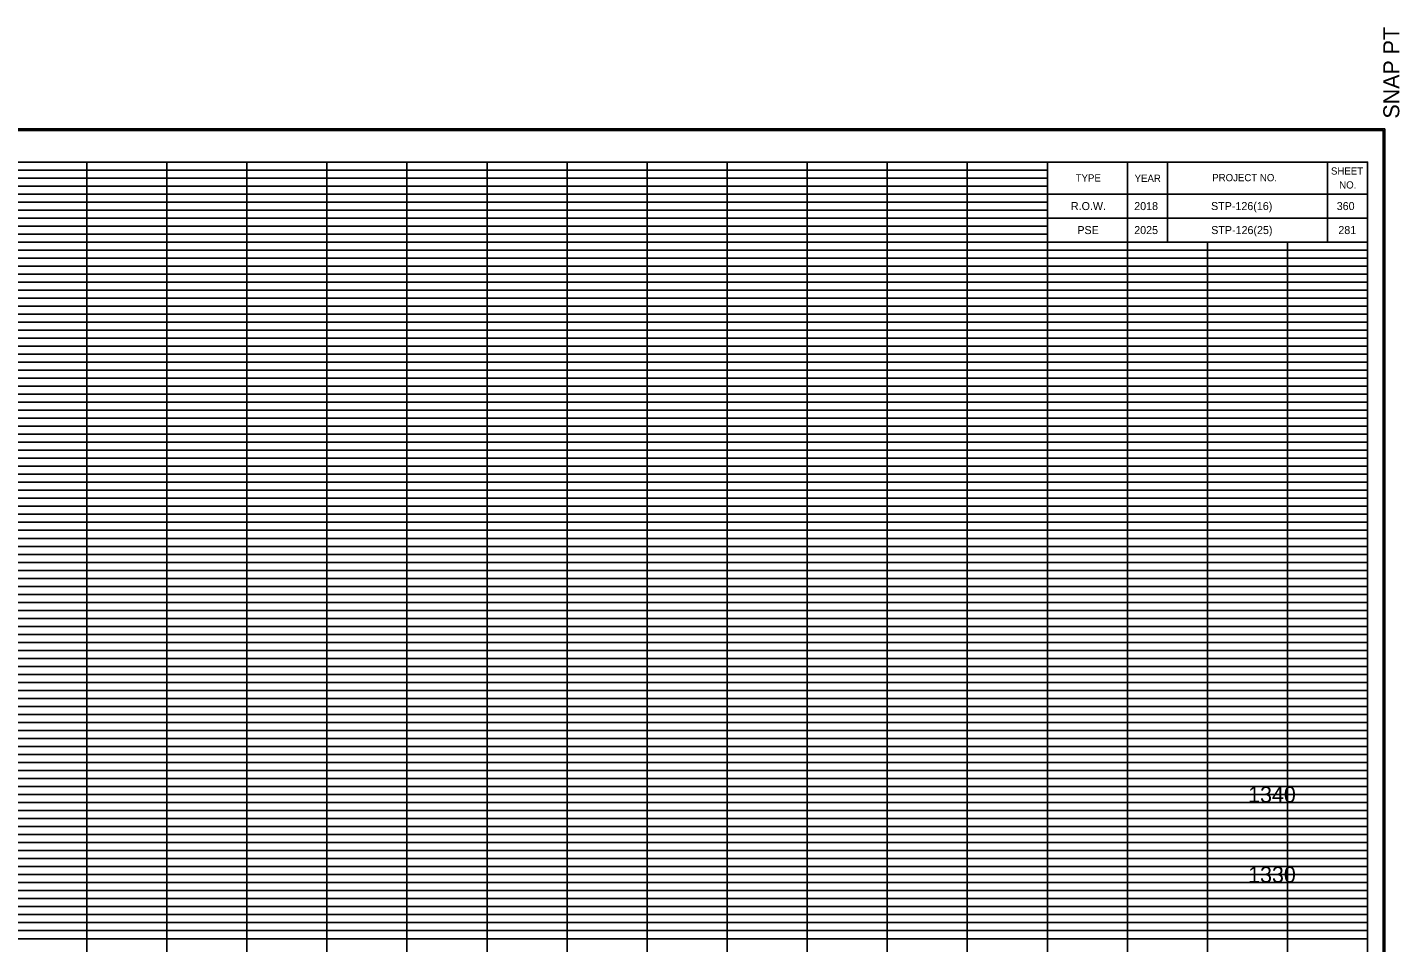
# Model space of a CAD drawing. Extents: x 980 to 1324, y 978 to 2847.
# Drawn here: x 1152.6 to 1324, y 1922.5 to 2036.8 of the extents above; entities that cross this region are included whole.
import ezdxf

# ---------------------------------------------------------------- set-up
doc = ezdxf.new("R2010")
doc.units = 0
for name, color, linetype in [('DESIGN - SCRATCH - User 1', 7, 'Continuous'), ('DESIGN - SHEET - Corner Text', 7, 'Continuous'), ('DESIGN - SHEET - Light Grid', 7, 'Continuous'), ('DESIGN - SHEET - Linework', 7, 'Continuous'), ('DESIGN - SHEET - Plot Shape', 7, 'Continuous'), ('DESIGN - TYPICAL - Text', 7, 'Continuous')]:
    doc.layers.add(name, color=color, linetype=linetype)

# ---------------------------------------------------------------- blocks, each defined once
blk = doc.blocks.new('XSTSHT')
at = {"layer": 'DESIGN - SCRATCH - User 1'}
for p, q in [((28.5, 20.45), (28.5, 20.45)), ((29.24, 20.45), (29.24, 20.45)), ((30.49, 20.45), (30.49, 20.45)), ((31.74, 20.45), (31.74, 20.45)), ((28.5, 20.15), (28.5, 20.15)), ((29.24, 20.15), (29.24, 20.15)), ((30.49, 20.15), (30.49, 20.15)), ((31.74, 20.15), (31.74, 20.15))]:
    blk.add_line(p, q, dxfattribs=at)
at = {"layer": 'DESIGN - SHEET - Light Grid'}
for p, q in [((8, 20.9), (16, 20.9)), ((8, 20.8), (16, 20.8)), ((16, 20.9), (24, 20.9)), ((16, 20.8), (24, 20.8)), ((24, 20.9), (28, 20.9)), ((24, 20.8), (28, 20.8)), ((8, 20.7), (16, 20.7)), ((8, 20.6), (16, 20.6)), ((16, 20.7), (24, 20.7)), ((16, 20.6), (24, 20.6)), ((24, 20.7), (28, 20.7)), ((24, 20.6), (28, 20.6)), ((8, 20.5), (16, 20.5)), ((8, 20.4), (16, 20.4)), ((16, 20.5), (24, 20.5)), ((16, 20.4), (24, 20.4)), ((24, 20.5), (28, 20.5)), ((24, 20.4), (28, 20.4)), ((8, 20.3), (16, 20.3)), ((16, 20.3), (24, 20.3)), ((24, 20.3), (28, 20.3)), ((8, 20.2), (16, 20.2)), ((8, 20.1), (16, 20.1)), ((16, 20.2), (24, 20.2)), ((16, 20.1), (24, 20.1)), ((24, 20.2), (28, 20.2)), ((24, 20.1), (28, 20.1)), ((8, 19.9), (16, 19.9)), ((16, 19.9), (24, 19.9)), ((24, 19.9), (32, 19.9)), ((8, 19.8), (16, 19.8)), ((16, 19.8), (24, 19.8)), ((24, 19.8), (32, 19.8)), ((8, 19.7), (16, 19.7)), ((8, 19.6), (16, 19.6)), ((16, 19.7), (24, 19.7)), ((16, 19.6), (24, 19.6)), ((24, 19.7), (32, 19.7)), ((24, 19.6), (32, 19.6)), ((8, 19.5), (16, 19.5)), ((8, 19.4), (16, 19.4)), ((16, 19.5), (24, 19.5)), ((16, 19.4), (24, 19.4)), ((24, 19.5), (32, 19.5)), ((24, 19.4), (32, 19.4)), ((8, 19.3), (16, 19.3)), ((8, 19.2), (16, 19.2)), ((16, 19.3), (24, 19.3)), ((16, 19.2), (24, 19.2)), ((24, 19.3), (32, 19.3)), ((24, 19.2), (32, 19.2)), ((8, 19.1), (16, 19.1)), ((16, 19.1), (24, 19.1)), ((24, 19.1), (32, 19.1)), ((8, 18.9), (16, 18.9)), ((16, 18.9), (24, 18.9)), ((24, 18.9), (32, 18.9)), ((8, 18.8), (16, 18.8)), ((8, 18.7), (16, 18.7)), ((16, 18.8), (24, 18.8)), ((16, 18.7), (24, 18.7)), ((24, 18.8), (32, 18.8)), ((24, 18.7), (32, 18.7)), ((8, 18.6), (16, 18.6)), ((16, 18.6), (24, 18.6)), ((24, 18.6), (32, 18.6)), ((8, 18.5), (16, 18.5)), ((8, 18.4), (16, 18.4)), ((16, 18.5), (24, 18.5)), ((16, 18.4), (24, 18.4)), ((24, 18.5), (32, 18.5)), ((24, 18.4), (32, 18.4)), ((8, 18.3), (16, 18.3)), ((8, 18.2), (16, 18.2)), ((16, 18.3), (24, 18.3)), ((16, 18.2), (24, 18.2)), ((24, 18.3), (32, 18.3)), ((24, 18.2), (32, 18.2)), ((8, 18.1), (16, 18.1)), ((16, 18.1), (24, 18.1)), ((24, 18.1), (32, 18.1)), ((8, 17.9), (16, 17.9)), ((16, 17.9), (24, 17.9)), ((24, 17.9), (32, 17.9)), ((8, 17.8), (16, 17.8)), ((8, 17.7), (16, 17.7)), ((16, 17.8), (24, 17.8)), ((16, 17.7), (24, 17.7)), ((24, 17.8), (32, 17.8)), ((24, 17.7), (32, 17.7)), ((8, 17.6), (16, 17.6)), ((8, 17.5), (16, 17.5)), ((16, 17.6), (24, 17.6)), ((16, 17.5), (24, 17.5)), ((24, 17.6), (32, 17.6)), ((24, 17.5), (32, 17.5)), ((8, 17.4), (16, 17.4)), ((16, 17.4), (24, 17.4)), ((24, 17.4), (32, 17.4)), ((8, 17.3), (16, 17.3)), ((8, 17.2), (16, 17.2)), ((16, 17.3), (24, 17.3)), ((16, 17.2), (24, 17.2)), ((24, 17.3), (32, 17.3)), ((24, 17.2), (32, 17.2)), ((8, 17.1), (16, 17.1)), ((16, 17.1), (24, 17.1)), ((24, 17.1), (32, 17.1)), ((8, 16.9), (16, 16.9)), ((8, 16.8), (16, 16.8)), ((16, 16.9), (24, 16.9)), ((16, 16.8), (24, 16.8)), ((24, 16.9), (32, 16.9)), ((24, 16.8), (32, 16.8)), ((8, 16.7), (16, 16.7)), ((16, 16.7), (24, 16.7)), ((24, 16.7), (32, 16.7)), ((8, 16.6), (16, 16.6)), ((8, 16.5), (16, 16.5)), ((16, 16.6), (24, 16.6)), ((16, 16.5), (24, 16.5)), ((24, 16.6), (32, 16.6)), ((24, 16.5), (32, 16.5)), ((8, 16.4), (16, 16.4)), ((8, 16.3), (16, 16.3)), ((16, 16.4), (24, 16.4)), ((16, 16.3), (24, 16.3)), ((24, 16.4), (32, 16.4)), ((24, 16.3), (32, 16.3)), ((8, 16.2), (16, 16.2)), ((16, 16.2), (24, 16.2)), ((24, 16.2), (32, 16.2)), ((8, 16.1), (16, 16.1)), ((16, 16.1), (24, 16.1)), ((24, 16.1), (32, 16.1)), ((8, 15.9), (16, 15.9)), ((8, 15.8), (16, 15.8)), ((16, 15.9), (24, 15.9)), ((16, 15.8), (24, 15.8)), ((24, 15.9), (32, 15.9)), ((24, 15.8), (32, 15.8)), ((8, 15.7), (16, 15.7)), ((8, 15.6), (16, 15.6)), ((16, 15.7), (24, 15.7)), ((16, 15.6), (24, 15.6)), ((24, 15.7), (32, 15.7)), ((24, 15.6), (32, 15.6)), ((8, 15.5), (16, 15.5)), ((16, 15.5), (24, 15.5)), ((24, 15.5), (32, 15.5)), ((8, 15.4), (16, 15.4)), ((8, 15.3), (16, 15.3)), ((16, 15.4), (24, 15.4)), ((16, 15.3), (24, 15.3)), ((24, 15.4), (32, 15.4)), ((24, 15.3), (32, 15.3)), ((8, 15.2), (16, 15.2)), ((8, 15.1), (16, 15.1)), ((16, 15.2), (24, 15.2)), ((16, 15.1), (24, 15.1)), ((24, 15.2), (32, 15.2)), ((24, 15.1), (32, 15.1)), ((8, 14.9), (16, 14.9)), ((8, 14.8), (16, 14.8)), ((16, 14.9), (24, 14.9)), ((16, 14.8), (24, 14.8)), ((24, 14.9), (32, 14.9)), ((24, 14.8), (32, 14.8)), ((8, 14.7), (16, 14.7)), ((8, 14.6), (16, 14.6)), ((16, 14.7), (24, 14.7)), ((16, 14.6), (24, 14.6)), ((24, 14.7), (32, 14.7)), ((24, 14.6), (32, 14.6)), ((8, 14.5), (16, 14.5)), ((8, 14.4), (16, 14.4)), ((16, 14.5), (24, 14.5)), ((16, 14.4), (24, 14.4)), ((24, 14.5), (32, 14.5)), ((24, 14.4), (32, 14.4)), ((8, 14.3), (16, 14.3)), ((16, 14.3), (24, 14.3)), ((24, 14.3), (32, 14.3)), ((8, 14.2), (16, 14.2)), ((8, 14.1), (16, 14.1)), ((16, 14.2), (24, 14.2)), ((16, 14.1), (24, 14.1)), ((24, 14.2), (32, 14.2)), ((24, 14.1), (32, 14.1)), ((8, 13.9), (16, 13.9)), ((16, 13.9), (24, 13.9)), ((24, 13.9), (32, 13.9)), ((8, 13.8), (16, 13.8)), ((16, 13.8), (24, 13.8)), ((24, 13.8), (32, 13.8)), ((8, 13.7), (16, 13.7)), ((8, 13.6), (16, 13.6)), ((16, 13.7), (24, 13.7)), ((16, 13.6), (24, 13.6)), ((24, 13.7), (32, 13.7)), ((24, 13.6), (32, 13.6)), ((8, 13.5), (16, 13.5)), ((8, 13.4), (16, 13.4)), ((16, 13.5), (24, 13.5)), ((16, 13.4), (24, 13.4)), ((24, 13.5), (32, 13.5)), ((24, 13.4), (32, 13.4)), ((8, 13.3), (16, 13.3)), ((8, 13.2), (16, 13.2)), ((16, 13.3), (24, 13.3)), ((16, 13.2), (24, 13.2)), ((24, 13.3), (32, 13.3)), ((24, 13.2), (32, 13.2)), ((8, 13.1), (16, 13.1)), ((16, 13.1), (24, 13.1)), ((24, 13.1), (32, 13.1)), ((8, 12.9), (16, 12.9)), ((16, 12.9), (24, 12.9)), ((24, 12.9), (32, 12.9)), ((8, 12.8), (16, 12.8)), ((8, 12.7), (16, 12.7)), ((16, 12.8), (24, 12.8)), ((16, 12.7), (24, 12.7)), ((24, 12.8), (32, 12.8)), ((24, 12.7), (32, 12.7)), ((8, 12.6), (16, 12.6)), ((16, 12.6), (24, 12.6)), ((24, 12.6), (32, 12.6)), ((8, 12.5), (16, 12.5)), ((8, 12.4), (16, 12.4)), ((16, 12.5), (24, 12.5)), ((16, 12.4), (24, 12.4)), ((24, 12.5), (32, 12.5)), ((24, 12.4), (32, 12.4)), ((8, 12.3), (16, 12.3)), ((8, 12.2), (16, 12.2)), ((16, 12.3), (24, 12.3)), ((16, 12.2), (24, 12.2)), ((24, 12.3), (32, 12.3)), ((24, 12.2), (32, 12.2)), ((8, 12.1), (16, 12.1)), ((16, 12.1), (24, 12.1)), ((24, 12.1), (32, 12.1)), ((8, 11.9), (16, 11.9)), ((16, 11.9), (24, 11.9)), ((24, 11.9), (32, 11.9)), ((8, 11.8), (16, 11.8)), ((8, 11.7), (16, 11.7)), ((16, 11.8), (24, 11.8)), ((16, 11.7), (24, 11.7)), ((24, 11.8), (32, 11.8)), ((24, 11.7), (32, 11.7)), ((8, 11.6), (16, 11.6)), ((8, 11.5), (16, 11.5)), ((16, 11.6), (24, 11.6)), ((16, 11.5), (24, 11.5)), ((24, 11.6), (32, 11.6)), ((24, 11.5), (32, 11.5)), ((8, 11.4), (16, 11.4)), ((16, 11.4), (24, 11.4)), ((24, 11.4), (32, 11.4)), ((8, 11.3), (16, 11.3)), ((16, 11.3), (24, 11.3)), ((24, 11.3), (32, 11.3))]:
    blk.add_line(p, q, dxfattribs=at)
at = {"layer": 'DESIGN - SHEET - Linework'}
for p, q in [((-1.823, 21.414), (32.217, 21.414)), ((32.217, 21.414), (32.217, -0.414)), ((16, 0), (16, 21)), ((17, 0), (17, 21)), ((18, 0), (18, 21)), ((19, 0), (19, 21)), ((20, 0), (20, 21)), ((21, 0), (21, 21)), ((22, 0), (22, 21)), ((23, 0), (23, 21)), ((24, 0), (24, 21)), ((25, 0), (25, 21)), ((26, 0), (26, 21)), ((27, 0), (27, 21)), ((0, 20), (28, 20)), ((28, 0), (28, 20)), ((29, 0), (29, 20)), ((30, 0), (30, 20)), ((31, 0), (31, 20)), ((0, 19), (32, 19)), ((0, 18), (32, 18)), ((0, 17), (32, 17)), ((0, 16), (32, 16)), ((0, 15), (32, 15)), ((0, 14), (32, 14)), ((0, 13), (32, 13)), ((0, 12), (32, 12))]:
    blk.add_line(p, q, dxfattribs=at)
for points in [[(0, 21), (0, 0), (32, 0), (32, 21), (0, 21)], [(28, 21), (28, 20), (32, 20), (32, 21), (31.5, 21), (31.5, 20), (29.5, 20), (29.5, 21), (29, 21), (29, 20), (32, 20), (28, 20), (28, 20.3), (32, 20.3), (32, 20.6), (28, 20.6)]]:
    blk.add_lwpolyline(points, dxfattribs=at)
at = {"layer": 'DESIGN - SHEET - Plot Shape'}
for points in [[(-1.803, 21.394), (32.197, 21.394), (32.197, -0.394), (-1.803, -0.394)], [(-0.85, 21), (32, 21), (32, -0.25), (-0.85, -0.25)]]:
    blk.add_lwpolyline(points, close=True, dxfattribs=at)
at = {"layer": 'DESIGN - SHEET - Corner Text'}
blk.add_text('  SNAP PT', height=0.2, rotation=90, dxfattribs=at).set_placement((32.397, 21.394))
for s, p in [('SHEET', (31.543, 20.843)), ('TYPE', (28.354, 20.756)), ('YEAR', (29.09, 20.752)), ('PROJECT NO.', (30.06, 20.76)), ('NO.', (31.646, 20.669))]:
    blk.add_text(s, height=0.09, dxfattribs=at).set_placement(p)

msp = doc.modelspace()

# ---------------------------------------------------------------- linework, layer by layer
at = {"layer": 'DESIGN - SHEET - Plot Shape'}
msp.add_lwpolyline([(991.5, 1807.5), (1320, 1807.5), (1320, 2020), (991.5, 2020)], close=True, dxfattribs=at)

# ---------------------------------------------------------------- block references
at = {"layer": 'DESIGN - SHEET - Plot Shape', "xscale": 10, "yscale": 10}
msp.add_blockref('XSTSHT', (1000, 1810), dxfattribs=at)

# ---------------------------------------------------------------- texts
at = {"layer": 'DESIGN - SHEET - Corner Text'}
for s, p in [('R.O.W.', (1282.94, 2014)), ('2018', (1290.85, 2014)), ('STP-126(16)', (1300.45, 2014)), ('360', (1316.15, 2014)), ('PSE', (1283.75, 2011)), ('2025', (1290.85, 2011)), ('STP-126(25)', (1300.47, 2011)), ('281', (1316.35, 2011))]:
    msp.add_text(s, height=1, dxfattribs=at).set_placement(p)
at = {"layer": 'DESIGN - TYPICAL - Text'}
for s, p in [('     1340     ', (1301.37, 1940)), ('     1330     ', (1301.37, 1930))]:
    msp.add_text(s, height=2, dxfattribs=at).set_placement(p)

doc.saveas('drawing.dxf')
